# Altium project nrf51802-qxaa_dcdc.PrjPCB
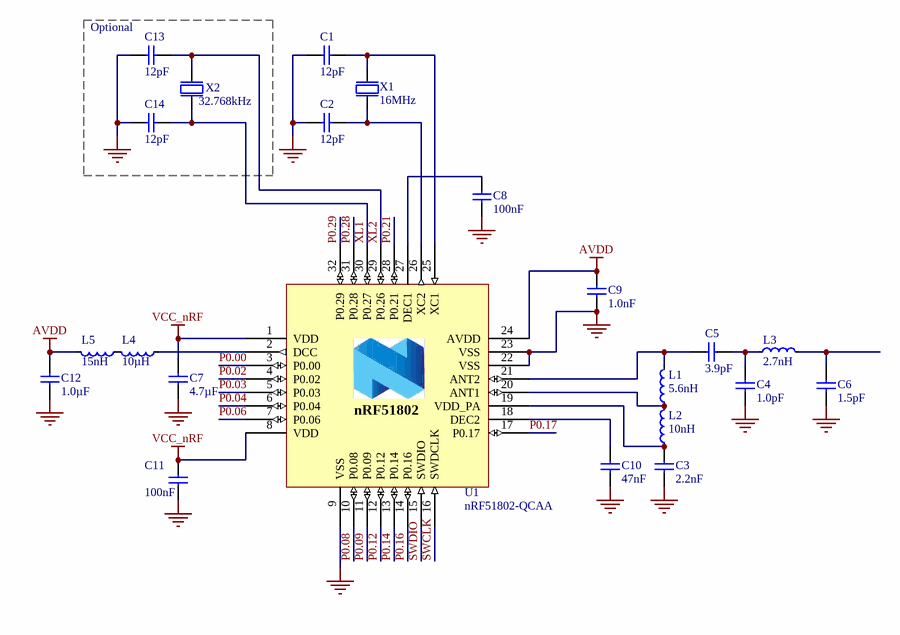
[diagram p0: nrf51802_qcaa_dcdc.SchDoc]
2 sheets, 44 parts. Net scope: global (net labels, ports and power ports of the same name join across sheets).
Board files: nrf51802_qcaa_dcdc.PcbDoc, nrf51802_qfaa_dcdc.PcbDoc
Sheets:
  nrf51802_qcaa_dcdc.SchDoc
  nrf51802_qfaa_dcdc.SchDoc

## Sheet nrf51802_qcaa_dcdc.SchDoc: nRF51802-QCAA Reference Layout (DCDC)
size A4; Revision: 1.0; SheetNumber: 1; SheetTotal: 1; DrawnBy: RUBR; DocumentSize: A4; PCAName: nRF51802-QCAA Reference Layout (DCDC)

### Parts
(Parts that share a designator on the sheet are numbered #1, #2 ... from top to bottom, then left to right.)
C1#1  12pF  [CAPC1005X04L]
C2#1  12pF  [CAPC1005X04L]
C3#1  2.2nF  [CAPC1005X04L]
C4#1  1.0pF  [CAPC1005X04L]
C5#1  3.9pF  [CAPC1005X04L]
C6#1  1.5pF  [CAPC1005X04L]
C7#1  4.7µF  [CAPC1608X06L]
C8#1  100nF  [CAPC1005X04L]
C9#1  1.0nF  [CAPC1005X04L]
C10#1  47nF  [CAPC1005X04L]
C11#1  100nF  [CAPC1005X04L]
C12#1  1.0µF  [CAPC1608X06L]
C13#1  12pF  [CAPC1005X04L]
C14#1  12pF  [CAPC1005X04L]
L1#1  5.6nH  [INDC1005X04L]
L2#1  10nH  [INDC1005X04L]
L3#1  2.7nH  [INDC1005X04L]
L4#1  10µH  [INDC1608X06L]
L5#1  15nH  [INDC1005X04L]
U1#1  nRF51802-QCAA  [Nordic_QFN50P500X500X90-33N]
X1#1  16MHz  [BT-XTAL_2520]
X2#1  32.768kHz  [XTAL_3215]

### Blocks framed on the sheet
Optional: C13#1 C14#1 X2#1

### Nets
AVDD: C9#1.1 C12#1.2 L5#1.2 U1#1.24(AVDD)
GND: C1#1.2 C2#1.2 C3#1.2 C4#1.2 C6#1.2 C7#1.2 C8#1.2 C9#1.2 C10#1.2 C11#1.2 C12#1.1 C13#1.1 C14#1.1 U1#1.9(VSS) U1#1.22(VSS) U1#1.23(VSS) U1#1.33 X1#1.2(GND) X1#1.4(GND)
VCC_nRF: C7#1.1 C11#1.1 U1#1.1(VDD) U1#1.8(VDD)
P0.00: U1#1.3(P0.00)
P0.02: U1#1.4(P0.02)
P0.03: U1#1.5(P0.03)
P0.04: U1#1.6(P0.04)
P0.06: U1#1.7(P0.06)
P0.08: U1#1.10(P0.08)
P0.09: U1#1.11(P0.09)
P0.12: U1#1.12(P0.12)
P0.14: U1#1.13(P0.14)
P0.16: U1#1.14(P0.16)
P0.17: U1#1.17(P0.17)
P0.21: U1#1.28(P0.21)
P0.28: U1#1.31(P0.28)
P0.29: U1#1.32(P0.29)
SWCLK: U1#1.16(SWDCLK)
SWDIO: U1#1.15(SWDIO)
XL1: C14#1.2 U1#1.30(P0.27) X2#1.2(out)
XL2: C13#1.2 U1#1.29(P0.26) X2#1.1(inp)
NetC1#1_1: C1#1.1 U1#1.25(XC1) X1#1.1(inp)
NetC2#1_1: C2#1.1 U1#1.26(XC2) X1#1.3(out)
NetC3#1_1: C3#1.1 L2#1.1 U1#1.19(VDD_PA)
NetC4#1_1: C4#1.1 C5#1.2 L3#1.1
NetC5#1_1: C5#1.1 L1#1.2 U1#1.21(ANT2)
NetC6#1_1: C6#1.1 L3#1.2
NetC8#1_1: C8#1.1 U1#1.27(DEC1)
NetC10#1_1: C10#1.1 U1#1.18(DEC2)
NetL1#1_1: L1#1.1 L2#1.2 U1#1.20(ANT1)
NetL4#1_1: L4#1.1 U1#1.2(DCC)
NetL4#1_2: L4#1.2 L5#1.1

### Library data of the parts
C1#1 C2#1 C13#1 C14#1 = C0402-12p: Capacitor, NP0, ±2%; Note: 50V; Artikkelnr Noca: 20029159; Artikkelnr Simpro: N.A.
C3#1 = C0402-2n2: Capacitor, X7R, ±10%; Note: 50V; Artikkelnr Noca: 20039221; Artikkelnr Simpro: N.A.
C4#1 = C0402-1.0p: Capacitor, NP0, ±0.1pF; Note: 50V; Artikkelnr Noca: 20029140; Artikkelnr Simpro: N.A.
C5#1 = C0402-3.9p: Capacitor, NP0, ±0.1pF; Note: 50V; Artikkelnr Noca: N.A.
C6#1 = C0402-1.5p: Capacitor, NP0, ±0.1pF; Note: 50V; Artikkelnr Noca: 20029139; Artikkelnr Simpro: N.A.
C7#1 = C0603-4µ7: Capacitor, X5R, ±10%; Note: 6.3V; Artikkelnr Noca: 20069060; Artikkelnr Simpro: N.A.
C8#1 C11#1 = C0402-100n: Capacitor, X7R, ±10%; Note: 16V; Artikkelnr Noca: 20039200; Artikkelnr Simpro: N.A.
C9#1 = C0402-1n0: Capacitor, X7R, ±10%; Note: 50V; Artikkelnr Noca: 20039223; Artikkelnr Simpro: N.A.
C10#1 = C0402-47n: Capacitor, X7R, ±10%; Note: Chip Cap 10%; Artikkelnr Noca: 20039389; Artikkelnr Simpro: N.A.
C12#1 = C0603-1µ0: Capacitor, X7R, ±10%; Note: 16V; Artikkelnr Noca: 20039335; Artikkelnr Simpro: N.A.
L1#1 = L0402-5n6: High frequency chip inductor ±5%; Manufacturer: Murata; Manufacturer Part Number: LQP15MN5N6B02D; Artikkelnr Noca: 33029161; Artikkelnr Simpro: N.A.
L2#1 = L0402-10n: High frequency chip inductor ±5%; Manufacturer: Murata; Manufacturer Part Number: LQP15MN10NG02D; Artikkelnr Noca: 33029425; Artikkelnr Simpro: N.A.
L3#1 = L0402-2n7: High frequency chip inductor ±5%; Manufacturer: Murata; Manufacturer Part Number: LQP15MN2N7B02D; Artikkelnr Noca: 33029150; Artikkelnr Simpro: N.A.
L4#1 = L0603-10µ: Chip inductor, IDC,min = 50 mA, ±20%; Manufacturer: Taiyo Yuden; Manufacturer Part Number: LBMF1608T100K; 2nd source part number: 178-6105; Note: LBMF1608T100K 10µH 80mA 0603; Artikkelnr Noca: 33029314; Artikkelnr Simpro: N.A.
L5#1 = L0402-15n: High frequency chip inductor ±10%; Manufacturer: Taiyo Yuden; Manufacturer Part Number: HK100515NJ-T; 2nd source part number: 658-1328; Artikkelnr Noca: 33029323; Artikkelnr Simpro: N.A.
U1#1 = nRF51802-QCAA: Multi-protocol Bluetooth Low Energy and 2.4GHz proprietary system-on-chip; Manufacturer: Nordic Semiconductor; Note: nRF51802 - QFN32 5x5 0.5mm pitch; Artikkelnr Noca: N.A.
X1#1 = XTAL_SMD2520_16MHz_8pF_NDK: XTAL SMD 2520, 16MHz, 8pF, ±40ppm; Manufacturer: NDK; Manufacturer Part Number: NX2520SA/16MHz/EXS00A-CS06713; Note: XTAL SMD 16.000MHz; Artikkelnr Noca: 22019192; Artikkelnr Simpro: N.A.
X2#1 = XTAL_FC-135 32.768k: XTAL SMD 3215, 32.768kHz, 9pF, ±20ppm; Manufacturer: Epson Toyocom; Manufacturer Part Number: FC-135 32.768KHZ ±20PPM,9.0PF; 2nd source part number: 127-8037; Note: XTAL SMD 32.768kHz, 3215; Artikkelnr Noca: 22019091; Artikkelnr Simpro: N.A.

## Sheet nrf51802_qfaa_dcdc.SchDoc: nRF51802-QFAA Reference Layout (DCDC)
size A4; Revision: 1.0; SheetNumber: 1; SheetTotal: 1; DrawnBy: RUBR; DocumentSize: A4; PCAName: nRF51802-QFAA Reference Layout (DCDC)
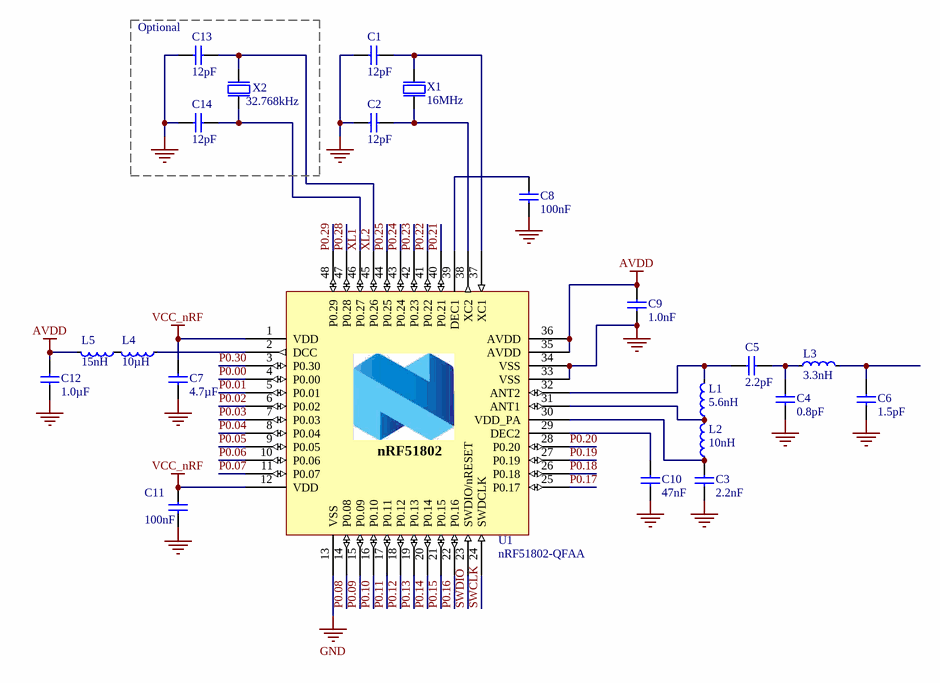
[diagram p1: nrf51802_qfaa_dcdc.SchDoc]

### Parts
(Parts that share a designator on the sheet are numbered #1, #2 ... from top to bottom, then left to right.)
C1#2  12pF  [CAPC1005X04L]
C2#2  12pF  [CAPC1005X04L]
C3#2  2.2nF  [CAPC1005X04L]
C4#2  0.8pF  [CAPC1005X04L]
C5#2  2.2pF  [CAPC1005X04L]
C6#2  1.5pF  [CAPC1005X04L]
C7#2  4.7µF  [CAPC1608X06L]
C8#2  100nF  [CAPC1005X04L]
C9#2  1.0nF  [CAPC1005X04L]
C10#2  47nF  [CAPC1005X04L]
C11#2  100nF  [CAPC1005X04L]
C12#2  1.0µF  [CAPC1608X06L]
C13#2  12pF  [CAPC1005X04L]
C14#2  12pF  [CAPC1005X04L]
L1#2  5.6nH  [INDC1005X04L]
L2#2  10nH  [INDC1005X04L]
L3#2  3.3nH  [INDC1005X04L]
L4#2  10µH  [INDC1608X06L]
L5#2  15nH  [INDC1005X04L]
U1#2  nRF51802-QFAA  [QFN40P600X600X90-48N]
X1#2  16MHz  [BT-XTAL_2520]
X2#2  32.768kHz  [XTAL_3215]

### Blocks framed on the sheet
Optional: C13#2 C14#2 X2#2

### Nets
AVDD: C9#2.1 C12#2.2 L5#2.2 U1#2.35(AVDD) U1#2.36(AVDD)
GND: C1#2.2 C2#2.2 C3#2.2 C4#2.2 C6#2.2 C7#2.2 C8#2.2 C9#2.2 C10#2.2 C11#2.2 C12#2.1 C13#2.1 C14#2.1 U1#2.13(VSS) U1#2.33(VSS) U1#2.34(VSS) U1#2.49 X1#2.2(GND) X1#2.4(GND)
VCC_nRF: C7#2.1 C11#2.1 U1#2.1(VDD) U1#2.12(VDD)
P0.00: U1#2.4(P0.00)
P0.01: U1#2.5(P0.01)
P0.02: U1#2.6(P0.02)
P0.03: U1#2.7(P0.03)
P0.04: U1#2.8(P0.04)
P0.05: U1#2.9(P0.05)
P0.06: U1#2.10(P0.06)
P0.07: U1#2.11(P0.07)
P0.08: U1#2.14(P0.08)
P0.09: U1#2.15(P0.09)
P0.10: U1#2.16(P0.10)
P0.11: U1#2.17(P0.11)
P0.12: U1#2.18(P0.12)
P0.13: U1#2.19(P0.13)
P0.14: U1#2.20(P0.14)
P0.15: U1#2.21(P0.15)
P0.16: U1#2.22(P0.16)
P0.17: U1#2.25(P0.17)
P0.18: U1#2.26(P0.18)
P0.19: U1#2.27(P0.19)
P0.20: U1#2.28(P0.20)
P0.21: U1#2.40(P0.21)
P0.22: U1#2.41(P0.22)
P0.23: U1#2.42(P0.23)
P0.24: U1#2.43(P0.24)
P0.25: U1#2.44(P0.25)
P0.28: U1#2.47(P0.28)
P0.29: U1#2.48(P0.29)
P0.30: U1#2.3(P0.30)
SWCLK: U1#2.24(SWDCLK)
SWDIO: U1#2.23(SWDIO/nRESET)
XL1: C14#2.2 U1#2.46(P0.27) X2#2.2(out)
XL2: C13#2.2 U1#2.45(P0.26) X2#2.1(inp)
NetC1#2_1: C1#2.1 U1#2.37(XC1) X1#2.1(inp)
NetC2#2_1: C2#2.1 U1#2.38(XC2) X1#2.3(out)
NetC3#2_1: C3#2.1 L2#2.1 U1#2.30(VDD_PA)
NetC4#2_1: C4#2.1 C5#2.2 L3#2.1
NetC5#2_1: C5#2.1 L1#2.2 U1#2.32(ANT2)
NetC6#2_1: C6#2.1 L3#2.2
NetC8#2_1: C8#2.1 U1#2.39(DEC1)
NetC10#2_1: C10#2.1 U1#2.29(DEC2)
NetL1#2_1: L1#2.1 L2#2.2 U1#2.31(ANT1)
NetL4#2_1: L4#2.1 U1#2.2(DCC)
NetL4#2_2: L4#2.2 L5#2.1

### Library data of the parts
C1#2 C2#2 C13#2 C14#2 = C0402-12p: as C1#1 on sheet nrf51802_qcaa_dcdc
C3#2 = C0402-2n2: as C3#1 on sheet nrf51802_qcaa_dcdc
C4#2 = C0402-0.8p: Capacitor, NP0, ±5%; Note: 50V; Artikkelnr Noca: 20029147; Artikkelnr Simpro: N.A.
C5#2 = C0402-2.2p: Capacitor, NP0, ±0.1pF; Note: 50V; Artikkelnr Noca: 20029145; Artikkelnr Simpro: N.A.
C6#2 = C0402-1.5p: as C6#1 on sheet nrf51802_qcaa_dcdc
C7#2 = C0603-4µ7: as C7#1 on sheet nrf51802_qcaa_dcdc
C8#2 C11#2 = C0402-100n: as C8#1 on sheet nrf51802_qcaa_dcdc
C9#2 = C0402-1n0: as C9#1 on sheet nrf51802_qcaa_dcdc
C10#2 = C0402-47n: as C10#1 on sheet nrf51802_qcaa_dcdc
C12#2 = C0603-1µ0: as C12#1 on sheet nrf51802_qcaa_dcdc
L1#2 = L0402-5n6: as L1#1 on sheet nrf51802_qcaa_dcdc
L2#2 = L0402-10n: as L2#1 on sheet nrf51802_qcaa_dcdc
L3#2 = L0402-3n3: High frequency chip inductor ±5%; Manufacturer: Murata; Manufacturer Part Number: LQP15MN3N3B02D; Artikkelnr Noca: 33029369; Artikkelnr Simpro: N.A.
L4#2 = L0603-10µ: as L4#1 on sheet nrf51802_qcaa_dcdc
L5#2 = L0402-15n: as L5#1 on sheet nrf51802_qcaa_dcdc
U1#2 = nRF51802-QFAA: Multi-protocol Bluetooth Low Energy and 2.4GHz proprietary system-on-chip; Manufacturer: Nordic Semiconductor; Note: nRF51802 - QFN48 6x6 0.4mm pitch; Artikkelnr Noca: N.A.
X1#2 = XTAL_SMD2520_16MHz_8pF_NDK: as X1#1 on sheet nrf51802_qcaa_dcdc
X2#2 = XTAL_FC-135 32.768k: as X2#1 on sheet nrf51802_qcaa_dcdc

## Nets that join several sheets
AVDD: nrf51802_qcaa_dcdc (C9#1.1 C12#1.2 L5#1.2 U1#1.24), nrf51802_qfaa_dcdc (5 pins)
GND: nrf51802_qcaa_dcdc (19 pins), nrf51802_qfaa_dcdc (19 pins)
VCC_nRF: nrf51802_qcaa_dcdc (C7#1.1 C11#1.1 U1#1.1 U1#1.8), nrf51802_qfaa_dcdc (C7#2.1 C11#2.1 U1#2.1 U1#2.12)
P0.00: nrf51802_qcaa_dcdc (U1#1.3), nrf51802_qfaa_dcdc (U1#2.4)
P0.02: nrf51802_qcaa_dcdc (U1#1.4), nrf51802_qfaa_dcdc (U1#2.6)
P0.03: nrf51802_qcaa_dcdc (U1#1.5), nrf51802_qfaa_dcdc (U1#2.7)
P0.04: nrf51802_qcaa_dcdc (U1#1.6), nrf51802_qfaa_dcdc (U1#2.8)
P0.06: nrf51802_qcaa_dcdc (U1#1.7), nrf51802_qfaa_dcdc (U1#2.10)
P0.08: nrf51802_qcaa_dcdc (U1#1.10), nrf51802_qfaa_dcdc (U1#2.14)
P0.09: nrf51802_qcaa_dcdc (U1#1.11), nrf51802_qfaa_dcdc (U1#2.15)
P0.12: nrf51802_qcaa_dcdc (U1#1.12), nrf51802_qfaa_dcdc (U1#2.18)
P0.14: nrf51802_qcaa_dcdc (U1#1.13), nrf51802_qfaa_dcdc (U1#2.20)
P0.16: nrf51802_qcaa_dcdc (U1#1.14), nrf51802_qfaa_dcdc (U1#2.22)
P0.17: nrf51802_qcaa_dcdc (U1#1.17), nrf51802_qfaa_dcdc (U1#2.25)
P0.21: nrf51802_qcaa_dcdc (U1#1.28), nrf51802_qfaa_dcdc (U1#2.40)
P0.28: nrf51802_qcaa_dcdc (U1#1.31), nrf51802_qfaa_dcdc (U1#2.47)
P0.29: nrf51802_qcaa_dcdc (U1#1.32), nrf51802_qfaa_dcdc (U1#2.48)
SWCLK: nrf51802_qcaa_dcdc (U1#1.16), nrf51802_qfaa_dcdc (U1#2.24)
SWDIO: nrf51802_qcaa_dcdc (U1#1.15), nrf51802_qfaa_dcdc (U1#2.23)
XL1: nrf51802_qcaa_dcdc (C14#1.2 U1#1.30 X2#1.2), nrf51802_qfaa_dcdc (C14#2.2 U1#2.46 X2#2.2)
XL2: nrf51802_qcaa_dcdc (C13#1.2 U1#1.29 X2#1.1), nrf51802_qfaa_dcdc (C13#2.2 U1#2.45 X2#2.1)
